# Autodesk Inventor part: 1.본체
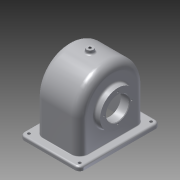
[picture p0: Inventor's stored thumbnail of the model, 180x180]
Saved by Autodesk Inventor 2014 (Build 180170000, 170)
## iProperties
Created: 2016-01
Part Number: 1.본체
Material: 알루미늄 6061
Document SubType Name: Modeling
Designer: SCD-A13
Density: 2.71 g/cm^3
Appearance: 알루미늄 - 평지
Mass: 808.189 g
Surface Area: 998.158 cm^2
Volume: 298.225 cm^3
Author: SCD-A13
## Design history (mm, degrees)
sketch "스케치1"
  geometry: L1 (-52, 70)-(52, 70); L2 (52, 70)-(52, -70); L3 (52, -70)-(-52, -70); L4 (-52, -70)-(-52, 70); 3 further points
  constraints: 8 end point, 2 midpoint, 2 parallel, 1 horizontal, 1 horizontal alignment, 1 perpendicular, 1 vertical alignment
  dimensions: "d0" = 140 distance of L3.end L1.start; "d1" = 104 distance of L1.start L1.end
extrude "돌출1" new body sketch "스케치1" distance "d2" = 7; taper "d3" = 0 deg
fillet "모깎기1" dims "d4" = 8
sketch "스케치3"
  geometry: A1 r 8 centre (-44, 62) between (-44, 70) and (-52, 62) reference; A2 r 8 centre (-44, -62) between (-52, -62) and (-44, -70) reference; A3 r 8 centre (44, -62) between (44, -70) and (52, -62) reference; A4 r 8 centre (44, 62) between (52, 62) and (44, 70) reference; 1 further point
hole "구멍1" sketch "스케치3" at (44, 62), (-44, 62), (-44, -62), (44, -62) diameter "d9" = 5; stored, may be unused: countersink angle "d13" = 90 deg, drill point angle "d15" = 118 deg; dims "d10" = 6, "d11" = 4, "d12" = 2, "d14" = 8
sketch "스케치7"
  geometry: L1 (-57, 0)-(57, 0); L2 (57, 0)-(57, 64); L3 (57, 64)-(-57, 64); L4 (-57, 64)-(-57, 0); L5 (-62, 0)-(62, 0) reference; A1 r 57 centre (0, 64) between (57, 64) and (-57, 64); 3 further points
  constraints: 8 end point, 3 midpoint, 2 parallel, 2 point on circle, 1 centre point, 1 coincident, 1 collinear, 1 horizontal, 1 perpendicular
  dimensions: "d24" = 64 distance of L3.end L1.start; "d25" = 114 distance of L2.end L3.end
extrude "돌출5" join sketch "스케치7" stored distance "d26" = 77; taper "d27" = 0 deg
sketch "스케치8"
  geometry: C1 r 31 at (-60, 0); 1 further point
  constraints: 1 centre point, 1 horizontal alignment
  dimensions: "d28" = 62 diameter of C1; "d29" = 60 distance of point (0, 0) C1.centre
extrude "돌출6" join sketch "스케치8" distance "d30" = 10; taper "d31" = 0 deg
sketch "스케치9"
  geometry: L1 (-51, 64)-(51, 64); L2 (51, 64)-(51, 0); L3 (51, 0)-(-51, 0); L4 (-51, 0)-(-51, 64); A1 r 57 centre (0, 64) between (57, 64) and (-57, 64) reference; A2 r 51 centre (0, 64) between (51, 64) and (-51, 64); 1 further point
  constraints: 8 end point, 2 parallel, 2 point on circle, 1 centre point, 1 horizontal, 1 perpendicular
  dimensions: "d32" = 6 radial gap between concentric circles of A1 A2; "d33" = 64 distance of L3.end L1.start; "d34" = 102 distance of L2.end L3.end
extrude "돌출7" cut sketch "스케치9" stored distance "d35" = 67; taper "d36" = 0 deg
sketch "스케치10"
  geometry: L1 (-48.5, 91)-(-48.5, 29) reference; L2 (-45.953, 60.779)-(38.5, 60.779); L3 (33.5, 100.527)-(19.5, 88.779); L4 (19.5, 88.779)-(19.5, 60.779); L5 (33.5, 100.527)-(33.5, 60.779); L6 (33.5, 64)-(33.5, 115) reference; L7 (38.5, 64)-(38.5, 7) reference; 1 further point
  constraints: 8 end point, 3 perpendicular, 3 point on line, 1 collinear
  dimensions: "d37" = 50 deg angle of L4 L3; "d38" = 28 distance of L3.end L4.end; "d39" = 19 distance of L2.end L4.end
revolve "회전1" sketch "스케치10" stored, may be unused: angle "d40" = 90 deg
hole "구멍2" diameter "d45" = 40; stored, may be unused: countersink angle "d49" = 90 deg, drill point angle "d51" = 118 deg; dims "d43" = 10, "d44" = 10, "d46" = 6, "d47" = 4, "d48" = 2, "d50" = 8
sketch "스케치13"
  geometry: L1 (38.5, 80)-(38.5, 40) reference; L2 (19.5, 40)-(19.5, 80) reference; L3 (38.5, 60)-(19.5, 60); L4 (38.5, 98.195)-(35.5, 95.678); L5 (35.5, 95.678)-(35.5, 60); L6 (19.5, 88.779)-(33.5, 100.527) reference; L7 (38.5, 98.195)-(38.5, 60); L8 (38.5, 64)-(38.5, 121) reference; 1 further point
  constraints: 8 end point, 2 midpoint, 2 point on line, 1 collinear, 1 parallel, 1 perpendicular
  dimensions: "d59" = 5 distance between parallel lines of L4 L6; "d60" = 3 distance between parallel lines of L5 L1; "d61" = 38.19501 distance of L4.start L7.end
revolve "회전2" sketch "스케치13" stored, may be unused: angle "d62" = 90 deg
node "작업 평면2"
  node "작업 평면1"
sketch "스케치14"
  geometry: C1 r 6 at (0, 0); 1 further point
  constraints: 1 centre point, 1 coincident
  dimensions: "d64" = 12 diameter of C1
extrude "돌출8" join sketch "스케치14" stored distance "d65" = 67; taper "d66" = 0 deg
hole "구멍3" diameter "d69" = 4.459; stored, may be unused: countersink angle "d73" = 90 deg, drill point angle "d75" = 118 deg; dims "d70" = 6, "d71" = 4, "d72" = 2, "d74" = 8, "d106" = 10, "d107" = 10
sketch "스케치15"
  geometry: L1 (60, 62)-(60, -62) reference; C1 r 20 at (0, 0) reference; 3 further points
  constraints: 1 horizontal alignment, 1 midpoint
  dimensions: "d76" = 24 distance of point (-24, 0) C1.centre
hole "구멍4" sketch "스케치15" at (-24, 0) diameter "d77" = 2.459; stored, may be unused: countersink angle "d81" = 90 deg, drill point angle "d83" = 118 deg; dims "d78" = 6, "d79" = 4, "d80" = 2, "d82" = 8
sketch "스케치16"
  geometry: L1 (0, -62)-(0, 62) reference; C1 r 38.195 at (60, 0) reference; 3 further points
  constraints: 1 horizontal alignment, 1 midpoint
  dimensions: "d87" = 28 distance of C1.centre point (88, 0)
hole "구멍5" sketch "스케치16" at (88, 0) diameter "d88" = 2.459; stored, may be unused: countersink angle "d92" = 90 deg, drill point angle "d94" = 118 deg; dims "d89" = 7, "d90" = 4, "d91" = 2, "d93" = 9
fillet "모깎기2" dims "d98" = 14
fillet "모깎기3" dims "d99" = 9
fillet "모깎기4" dims "d100" = 3
fillet "모깎기5" dims "d101" = 1
fillet "모깎기6" dims "d102" = 3
chamfer "모따기1" distance "d103" = 1; stored, may be unused: second distance "d104" = 2, angle "d105" = 45 deg
node "솔리드1"
pattern_circular "원형 패턴1" dims angle "d85" = 360 deg
pattern_circular "원형 패턴2" dims angle "d96" = 360 deg
other parameters: "d63" = 6
